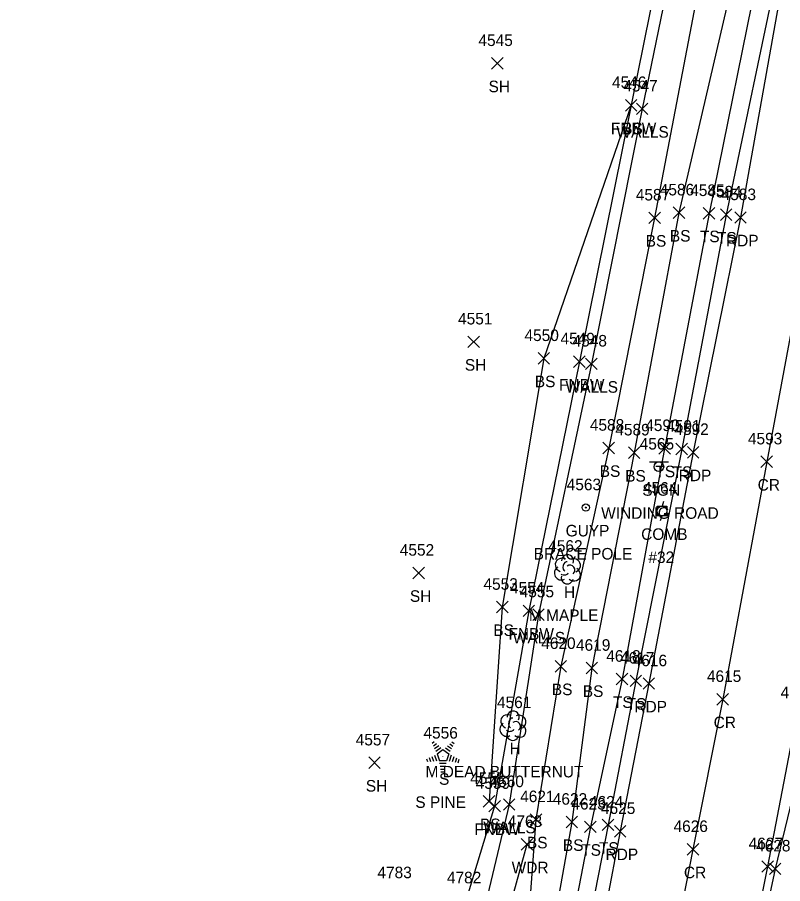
# Model space of a CAD drawing. Extents: x 1678863 to 1683592, y 407783 to 418211.
# Drawn here: x 1680118.7 to 1680251.2, y 412556.9 to 412706.9 of the extents above; entities that cross this region are included whole.
import ezdxf

# ---------------------------------------------------------------- set-up
doc = ezdxf.new("R2010")
doc.units = 0
for name, color, linetype in [('L_A', 7, 'Continuous'), ('L_C', 7, 'Continuous'), ('L_I', 7, 'Continuous'), ('L_TIC', 7, 'Continuous'), ('LAWA', 7, 'Continuous'), ('LELB', 7, 'Continuous'), ('LFNC', 7, 'Continuous'), ('LTC', 7, 'Continuous'), ('LTD', 7, 'Continuous'), ('LWS', 7, 'Continuous'), ('P_A', 7, 'Continuous'), ('P_I', 7, 'Continuous'), ('P_TIC', 7, 'Continuous'), ('PET', 7, 'Continuous'), ('PRC', 7, 'Continuous'), ('S_A', 7, 'Continuous'), ('S_C', 7, 'Continuous'), ('S_I', 7, 'Continuous'), ('SSGN', 7, 'Continuous'), ('U_A', 7, 'Continuous'), ('U_C', 7, 'Continuous'), ('U_I', 7, 'Continuous'), ('UP', 7, 'Continuous'), ('UPGW', 7, 'Continuous')]:
    doc.layers.add(name, color=color, linetype=linetype)

msp = doc.modelspace()

# ---------------------------------------------------------------- linework, layer by layer
at = {"layer": 'L_TIC'}
for points in [[(1680200.8, 412697.96), (1680202.8, 412699.96)], [(1680202.8, 412697.96), (1680200.8, 412699.96)], [(1680223.98, 412690.69), (1680225.98, 412692.69)], [(1680225.98, 412690.69), (1680223.98, 412692.69)], [(1680223.98, 412690.69), (1680225.98, 412692.69)], [(1680225.98, 412690.69), (1680223.98, 412692.69)], [(1680225.88, 412690.09), (1680227.88, 412692.09)], [(1680227.88, 412690.09), (1680225.88, 412692.09)], [(1680232.25, 412672.09), (1680234.25, 412674.09)], [(1680234.25, 412672.09), (1680232.25, 412674.09)], [(1680237.47, 412671.98), (1680239.47, 412673.98)], [(1680239.47, 412671.98), (1680237.47, 412673.98)], [(1680228.05, 412671.21), (1680230.05, 412673.21)], [(1680230.05, 412671.21), (1680228.05, 412673.21)], [(1680240.43, 412671.74), (1680242.43, 412673.74)], [(1680242.43, 412671.74), (1680240.43, 412673.74)], [(1680196.7, 412649.74), (1680198.7, 412651.74)], [(1680198.7, 412649.74), (1680196.7, 412651.74)], [(1680208.86, 412646.87), (1680210.86, 412648.87)], [(1680210.86, 412646.87), (1680208.86, 412648.87)], [(1680215.02, 412646.3), (1680217.02, 412648.3)], [(1680217.02, 412646.3), (1680215.02, 412648.3)], [(1680217.1, 412645.92), (1680219.1, 412647.92)], [(1680219.1, 412645.92), (1680217.1, 412647.92)], [(1680220.09, 412631.34), (1680222.09, 412633.34)], [(1680222.09, 412631.34), (1680220.09, 412633.34)], [(1680224.51, 412630.52), (1680226.51, 412632.52)], [(1680226.51, 412630.52), (1680224.51, 412632.52)], [(1680229.77, 412631.28), (1680231.77, 412633.28)], [(1680231.77, 412631.28), (1680229.77, 412633.28)], [(1680232.74, 412631.17), (1680234.74, 412633.17)], [(1680234.74, 412631.17), (1680232.74, 412633.17)], [(1680187.18, 412609.7), (1680189.18, 412611.7)], [(1680189.18, 412609.7), (1680187.18, 412611.7)], [(1680201.67, 412603.79), (1680203.67, 412605.79)], [(1680203.67, 412603.79), (1680201.67, 412605.79)], [(1680206.26, 412603.15), (1680208.26, 412605.15)], [(1680208.26, 412603.15), (1680206.26, 412605.15)], [(1680207.94, 412602.49), (1680209.94, 412604.49)], [(1680209.94, 412602.49), (1680207.94, 412604.49)], [(1680211.81, 412593.54), (1680213.81, 412595.54)], [(1680213.81, 412593.54), (1680211.81, 412595.54)], [(1680217.17, 412593.23), (1680219.17, 412595.23)], [(1680219.17, 412593.23), (1680217.17, 412595.23)], [(1680222.41, 412591.33), (1680224.41, 412593.33)], [(1680224.41, 412591.33), (1680222.41, 412593.33)], [(1680224.8, 412591.02), (1680226.8, 412593.02)], [(1680226.8, 412591.02), (1680224.8, 412593.02)], [(1680179.55, 412576.84), (1680181.55, 412578.84)], [(1680181.55, 412576.84), (1680179.55, 412578.84)], [(1680199.37, 412570.16), (1680201.37, 412572.16)], [(1680201.37, 412570.16), (1680199.37, 412572.16)], [(1680200.33, 412569.32), (1680202.33, 412571.32)], [(1680202.33, 412569.32), (1680200.33, 412571.32)], [(1680202.86, 412569.61), (1680204.86, 412571.61)], [(1680204.86, 412569.61), (1680202.86, 412571.61)], [(1680207.5, 412567.01), (1680209.5, 412569.01)], [(1680209.5, 412567.01), (1680207.5, 412569.01)], [(1680213.71, 412566.57), (1680215.71, 412568.57)], [(1680215.71, 412566.57), (1680213.71, 412568.57)], [(1680216.93, 412565.73), (1680218.93, 412567.73)], [(1680218.93, 412565.73), (1680216.93, 412567.73)], [(1680219.98, 412566.08), (1680221.98, 412568.08)], [(1680221.98, 412566.08), (1680219.98, 412568.08)], [(1680205.93, 412562.7), (1680207.93, 412564.7)], [(1680207.93, 412562.7), (1680205.93, 412564.7)], [(1680248.92, 412558.47), (1680250.92, 412560.47)], [(1680250.92, 412558.47), (1680248.92, 412560.47)]]:
    msp.add_lwpolyline(points, dxfattribs=at)
at = {"layer": 'LAWA'}
msp.add_lwpolyline([(1680206.93, 412563.7), (1680202.04, 412545.92), (1680195.91, 412512.78), (1680188.89, 412485.66), (1680186.26, 412471.76), (1680180.56, 412450.61), (1680168.77, 412423.38), (1680176.3, 412418.61), (1680169.98, 412398.15), (1680162.84, 412369.71), (1680155.02, 412336.92), (1680137.08, 412306.47), (1680135.2, 412293), (1680118.69, 412249.85)], dxfattribs=at)
at = {"layer": 'LELB'}
for points in [[(1680264.76, 412811.55), (1680263.36, 412796.82), (1680259.13, 412765.17), (1680254.89, 412741.7), (1680250.64, 412716.52), (1680241.43, 412672.74), (1680233.74, 412632.17), (1680225.8, 412592.02), (1680220.98, 412567.08), (1680215.74, 412540.31), (1680209.94, 412509.25), (1680204.22, 412481.07), (1680197.27, 412449.21), (1680193.18, 412427.19), (1680186.13, 412390.36), (1680174.63, 412348.27), (1680162.56, 412311.44), (1680153.21, 412285.21), (1680144.52, 412262.81), (1680134.21, 412242.14)], [(1680249.49, 412768.2), (1680249.55, 412758.24), (1680243.8, 412718.57), (1680233.25, 412673.09), (1680225.51, 412631.52), (1680218.17, 412594.23), (1680214.71, 412567.57), (1680210.01, 412541.36), (1680205.47, 412510.43), (1680201.22, 412481.17), (1680196.31, 412449.36), (1680192.42, 412427.44), (1680185.73, 412390.56), (1680174.21, 412348.31), (1680162.14, 412311.42), (1680152.66, 412285.29), (1680142.36, 412263.76), (1680132.21, 412242.7)], [(1680245.33, 412759.55), (1680238.15, 412719.92), (1680229.05, 412672.21), (1680221.09, 412632.34), (1680212.81, 412594.54), (1680208.5, 412568.01), (1680206.55, 412542.12), (1680201.64, 412511.16), (1680199.02, 412481.87), (1680194.17, 412449.89), (1680191.64, 412427.54), (1680187.79, 412410.87)], [(1680247.45, 412717.1), (1680238.47, 412672.98), (1680230.77, 412632.28), (1680223.41, 412592.33), (1680217.93, 412566.73), (1680212.88, 412540.48)], [(1680224.98, 412691.69), (1680209.86, 412647.87), (1680202.67, 412604.79), (1680200.37, 412571.16)], [(1680298.44, 412568.57), (1680284.88, 412583.01), (1680266.88, 412595.61), (1680260.41, 412601.01), (1680256.27, 412585.74), (1680249.92, 412559.47), (1680243.91, 412531.33), (1680236.6, 412492.51), (1680228.82, 412454.39), (1680218.5, 412406.89), (1680208.69, 412367.35), (1680198.1, 412331.27), (1680190.23, 412308.46), (1680180.36, 412277.86), (1680168.7, 412243.07)]]:
    msp.add_lwpolyline(points, dxfattribs=at)
at = {"layer": 'LFNC'}
msp.add_lwpolyline([(1680218.33, 412787.64), (1680231.24, 412777.54), (1680236.8, 412767.88), (1680237.55, 412751.41), (1680232.55, 412729.19), (1680224.98, 412691.69), (1680216.02, 412647.3), (1680207.26, 412604.15), (1680201.33, 412570.32), (1680196.34, 412553.95), (1680191.84, 412524.59), (1680188.15, 412511.78), (1680185.17, 412500.91), (1680174.35, 412504.66)], dxfattribs=at)
at = {"layer": 'LTC'}
for p, q in [((1680190.53, 412581.23), (1680190.89, 412581.49)), ((1680190.74, 412580.77), (1680191.27, 412581.15)), ((1680193.56, 412581.12), (1680194.11, 412580.72)), ((1680193.93, 412581.47), (1680194.35, 412581.17)), ((1680190.95, 412580.3), (1680191.66, 412580.81)), ((1680191.16, 412579.83), (1680192.04, 412580.47)), ((1680191.39, 412579.38), (1680192.4, 412580.11)), ((1680191.39, 412579.38), (1680191.77, 412578.19)), ((1680192.4, 412580.11), (1680193.39, 412579.39)), ((1680192.82, 412580.43), (1680193.63, 412579.84)), ((1680193.39, 412579.39), (1680193, 412578.19)), ((1680193.19, 412580.77), (1680193.87, 412580.28)), ((1680189.56, 412578.51), (1680189.72, 412578.04)), ((1680190.02, 412578.73), (1680190.23, 412578.07)), ((1680190.48, 412578.94), (1680190.75, 412578.11)), ((1680190.93, 412579.16), (1680191.26, 412578.14)), ((1680193, 412578.19), (1680191.77, 412578.19)), ((1680193.83, 412579.12), (1680193.49, 412578.08)), ((1680194.28, 412578.87), (1680193.99, 412577.98)), ((1680194.72, 412578.62), (1680194.48, 412577.89)), ((1680195.17, 412578.37), (1680194.98, 412577.79)), ((1680192.96, 412577.69), (1680191.82, 412577.69)), ((1680192.88, 412577.19), (1680191.89, 412577.19)), ((1680192.8, 412576.69), (1680191.97, 412576.69)), ((1680192.71, 412576.19), (1680192.04, 412576.19))]:
    msp.add_line(p, q, dxfattribs=at)
at = {"layer": 'LTD'}
for p, q in [((1680213.92, 412611.38), (1680213.92, 412611.38)), ((1680213.92, 412611.38), (1680213.92, 412611.38)), ((1680204.49, 412584.3), (1680204.49, 412584.3)), ((1680204.49, 412584.3), (1680204.49, 412584.3))]:
    msp.add_line(p, q, dxfattribs=at)
for centre in [(1680213.97, 412612.82), (1680204.54, 412585.73)]:
    msp.add_arc(centre, 1.05, 335.5272, 180.9563, dxfattribs=at)
for centre, major_axis, ratio, start_param, end_param in [((1680213.13, 412612.05), (1.21, -0.51), 0.895232, 1.570796, 4.712389), ((1680213.72, 412611.84), (-0.208, -0.792), 0.645439, 3.141593, 6.283185), ((1680214.97, 412611.97), (-1.14, -0.48), 0.949671, 1.570796, 4.712389), ((1680212.84, 412610.67), (0.58, -1.04), 0.959034, 3.141593, 6.283185), ((1680214.42, 412611.22), (-0.5, 0.667), 0.989748, 3.141593, 6.283185), ((1680214.92, 412610.55), (-1.09, 0.79), 0.841452, 1.570796, 4.712389), ((1680213.92, 412609.88), (0.26, 1.06), 0.942809, 1.570796, 4.712389), ((1680213.47, 412610.63), (-0.625, -0.083), 0.423636, 0, 3.141593), ((1680203.7, 412584.96), (1.21, -0.51), 0.895232, 1.570796, 4.712389), ((1680204.29, 412584.76), (-0.208, -0.792), 0.645439, 3.141593, 6.283185), ((1680205.54, 412584.88), (-1.14, -0.48), 0.949671, 1.570796, 4.712389), ((1680203.41, 412583.59), (0.58, -1.04), 0.959034, 3.141593, 6.283185), ((1680204.99, 412584.13), (-0.5, 0.667), 0.989748, 3.141593, 6.283185), ((1680205.49, 412583.46), (-1.09, 0.79), 0.841452, 1.570796, 4.712389), ((1680204.49, 412582.8), (0.26, 1.06), 0.942809, 1.570796, 4.712389), ((1680204.04, 412583.55), (-0.625, -0.083), 0.423636, 0, 3.141593)]:
    msp.add_ellipse(centre, major_axis=major_axis, ratio=ratio, start_param=start_param, end_param=end_param, dxfattribs=at)
at = {"layer": 'LWS'}
msp.add_lwpolyline([(1680245.37, 412777.27), (1680244.27, 412770.72), (1680239.06, 412752.16), (1680234.49, 412728.17), (1680226.88, 412691.09), (1680218.1, 412646.92), (1680208.94, 412603.49), (1680203.86, 412570.61), (1680197.52, 412543.94), (1680191.67, 412514.8), (1680187.87, 412497.52)], dxfattribs=at)
at = {"layer": 'P_TIC'}
for points in [[(1680242.91, 412671.27), (1680244.91, 412673.27)], [(1680244.91, 412671.27), (1680242.91, 412673.27)], [(1680234.73, 412630.6), (1680236.73, 412632.6)], [(1680236.73, 412630.6), (1680234.73, 412632.6)], [(1680247.46, 412628.97), (1680249.46, 412630.97)], [(1680249.46, 412628.97), (1680247.46, 412630.97)], [(1680227.05, 412590.55), (1680229.05, 412592.55)], [(1680229.05, 412590.55), (1680227.05, 412592.55)], [(1680239.84, 412587.83), (1680241.84, 412589.83)], [(1680241.84, 412587.83), (1680239.84, 412589.83)], [(1680222.07, 412564.97), (1680224.07, 412566.97)], [(1680224.07, 412564.97), (1680222.07, 412566.97)], [(1680234.69, 412561.84), (1680236.69, 412563.84)], [(1680236.69, 412561.84), (1680234.69, 412563.84)], [(1680247.62, 412558.86), (1680249.62, 412560.86)], [(1680249.62, 412558.86), (1680247.62, 412560.86)]]:
    msp.add_lwpolyline(points, dxfattribs=at)
at = {"layer": 'PET'}
for points in [[(1680296.3, 412834.01), (1680292.92, 412809.88), (1680289.09, 412781.37), (1680282.07, 412737.34), (1680277.46, 412709.86), (1680269.38, 412667.98), (1680262.24, 412629.4), (1680258.01, 412607.41), (1680253.6, 412586.01), (1680248.62, 412559.86), (1680242.91, 412531.6), (1680235.26, 412492.91), (1680227.56, 412454.34), (1680216.99, 412407.09), (1680207.45, 412367.83), (1680196.86, 412331.66), (1680189.42, 412308.79), (1680178.4, 412278.7), (1680165.09, 412243.62)], [(1680269.63, 412829.2), (1680265.04, 412796.13), (1680259.96, 412765.02), (1680256.28, 412741.52), (1680251.79, 412716.36), (1680243.91, 412672.27), (1680235.73, 412631.6), (1680228.05, 412591.55), (1680223.07, 412565.97), (1680218.11, 412539.91), (1680211.61, 412508.58), (1680205.85, 412480.93), (1680199.66, 412448.83), (1680195.01, 412427.07), (1680186.54, 412390.39), (1680175.26, 412348.31), (1680163.41, 412311.1), (1680153.81, 412285.2), (1680145.32, 412262.57), (1680136.24, 412241.39)]]:
    msp.add_lwpolyline(points, dxfattribs=at)
at = {"layer": 'PRC'}
msp.add_lwpolyline([(1680281.38, 412827.12), (1680276.54, 412794.32), (1680271.51, 412761.65), (1680263.6, 412713.37), (1680255.9, 412669.93), (1680248.46, 412629.97), (1680240.84, 412588.83), (1680235.69, 412562.84), (1680230.13, 412534.53), (1680222.13, 412495.39), (1680214.42, 412458.66), (1680203.73, 412409.82), (1680194.11, 412372.14), (1680183.59, 412335.84), (1680176.01, 412313.28), (1680165.53, 412283.79), (1680155.94, 412258.65)], dxfattribs=at)
at = {"layer": 'SSGN'}
for p, q in [((1680228.14, 412629.93), (1680231.47, 412629.93)), ((1680229.78, 412629.1), (1680229.78, 412629.1))]:
    msp.add_line(p, q, dxfattribs=at)
msp.add_circle((1680229.78, 412629.1), 0.833, dxfattribs=at)
at = {"layer": 'UP'}
for p, q in [((1680230.58, 412623.1), (1680230.33, 412622.27)), ((1680229.5, 412620.6), (1680229.5, 412622.27)), ((1680229.5, 412622.27), (1680231.16, 412622.27)), ((1680230.33, 412621.43), (1680230.33, 412621.43)), ((1680231.16, 412622.27), (1680231.16, 412620.6)), ((1680231.16, 412620.6), (1680229.5, 412620.6)), ((1680230.08, 412619.77), (1680230.33, 412620.6))]:
    msp.add_line(p, q, dxfattribs=at)
msp.add_circle((1680230.33, 412621.43), 0.833, dxfattribs=at)
at = {"layer": 'UPGW'}
for radius in [0.625, 0.0833]:
    msp.add_circle((1680217.13, 412622.03), radius, dxfattribs=at)

# ---------------------------------------------------------------- texts
at = {"layer": 'L_A'}
for s, p in [('SH', (1680200.29, 412693.96)), ('FNBW', (1680221.46, 412686.69)), ('WALLS', (1680222.43, 412686.09)), ('BS', (1680223.42, 412686.69)), ('BS', (1680231.69, 412668.09)), ('TS', (1680236.88, 412667.98)), ('TS', (1680239.84, 412667.74)), ('BS', (1680227.5, 412667.21)), ('SH', (1680196.19, 412645.74)), ('BS', (1680208.3, 412642.87)), ('FNBW', (1680212.49, 412642.3)), ('WALLS', (1680213.64, 412641.92)), ('BS', (1680219.54, 412627.34)), ('TS', (1680229.18, 412627.28)), ('TS', (1680232.15, 412627.17)), ('BS', (1680223.95, 412626.52)), ('H', (1680213.36, 412606.38)), ('SH', (1680186.67, 412605.7)), ('BS', (1680201.12, 412599.79)), ('FNBW', (1680203.74, 412599.15)), ('WALLS', (1680204.49, 412598.49)), ('BS', (1680211.25, 412589.54)), ('BS', (1680216.61, 412589.23)), ('TS', (1680221.82, 412587.33)), ('TS', (1680224.21, 412587.02)), ('H', (1680203.93, 412579.3)), ('SH', (1680179.04, 412572.84)), ('S', (1680191.72, 412574.02)), ('BS', (1680198.82, 412566.16)), ('WALLS', (1680199.4, 412565.61)), ('FNBW', (1680197.81, 412565.32)), ('BS', (1680206.94, 412563.01)), ('BS', (1680213.16, 412562.57)), ('TS', (1680216.34, 412561.73)), ('TS', (1680219.39, 412562.08)), ('WDR', (1680204.29, 412558.7))]:
    msp.add_text(s, height=2, dxfattribs=at).set_placement(p)
at = {"layer": 'L_C'}
for s, p in [('M MAPLE', (1680207.28, 412602.38)), ('M DEAD BUTTERNUT', (1680189.38, 412575.3)), ('S PINE', (1680187.61, 412570.02))]:
    msp.add_text(s, height=2, dxfattribs=at).set_placement(p)
at = {"layer": 'L_I'}
for s, p in [('4545', (1680198.54, 412701.96)), ('4546', (1680221.67, 412694.69)), ('4546', (1680221.67, 412694.69)), ('4547', (1680223.62, 412694.09)), ('4587', (1680225.79, 412675.21)), ('4586', (1680229.94, 412676.09)), ('4585', (1680235.21, 412675.98)), ('4584', (1680238.17, 412675.74)), ('4551', (1680195.01, 412653.74)), ('4550', (1680206.51, 412650.87)), ('4549', (1680212.75, 412650.3)), ('4548', (1680214.84, 412649.92)), ('4588', (1680217.83, 412635.34)), ('4589', (1680222.24, 412634.52)), ('4590', (1680227.42, 412635.28)), ('4591', (1680231.05, 412635.17)), ('4552', (1680184.92, 412613.7)), ('4562', (1680210.62, 412614.38)), ('4553', (1680199.41, 412607.79)), ('4554', (1680204, 412607.15)), ('4555', (1680205.68, 412606.49)), ('4620', (1680209.41, 412597.54)), ('4619', (1680215.43, 412597.23)), ('4618', (1680220.67, 412595.33)), ('4617', (1680223.06, 412595.02)), ('4561', (1680201.75, 412587.3)), ('4556', (1680189.02, 412582.02)), ('4557', (1680177.29, 412580.84)), ('4558', (1680197.11, 412574.16)), ('4559', (1680198.07, 412573.32)), ('4560', (1680200.46, 412573.61)), ('4621', (1680205.76, 412571.01)), ('4622', (1680211.41, 412570.57)), ('4624', (1680217.68, 412570.08)), ('4623', (1680214.63, 412569.73)), ('4763', (1680203.62, 412566.7)), ('4628', (1680246.62, 412562.47)), ('4783', (1680181.05, 412557.84)), ('4782', (1680193.08, 412556.95)), ('4782', (1680193.08, 412556.95))]:
    msp.add_text(s, height=2, dxfattribs=at).set_placement(p)
at = {"layer": 'LTC'}
msp.add_text('.', height=1.04, rotation=270, dxfattribs=at).set_placement((1680192.28, 412579.13))
at = {"layer": 'P_A'}
for s, p in [('RDP', (1680241.4, 412667.27)), ('RDP', (1680233.22, 412626.6)), ('CR', (1680246.89, 412624.97)), ('RDP', (1680225.54, 412586.55)), ('CR', (1680239.27, 412583.83)), ('RDP', (1680220.55, 412560.97)), ('CR', (1680234.12, 412557.84))]:
    msp.add_text(s, height=2, dxfattribs=at).set_placement(p)
at = {"layer": 'P_I'}
for s, p in [('4583', (1680240.65, 412675.27)), ('4592', (1680232.47, 412634.6)), ('4593', (1680245.2, 412632.97)), ('4616', (1680225.25, 412594.55)), ('4615', (1680238.1, 412591.83)), ('4614', (1680250.86, 412589.01)), ('4625', (1680219.76, 412568.97)), ('4626', (1680232.32, 412565.84)), ('4627', (1680245.32, 412562.86))]:
    msp.add_text(s, height=2, dxfattribs=at).set_placement(p)
at = {"layer": 'S_A'}
msp.add_text('SIGN', height=2, dxfattribs=at).set_placement((1680226.92, 412624.08))
at = {"layer": 'S_C'}
msp.add_text('WINDING ROAD', height=2, dxfattribs=at).set_placement((1680219.79, 412620.08))
at = {"layer": 'S_I'}
msp.add_text('4565', height=2, dxfattribs=at).set_placement((1680226.46, 412632.08))
at = {"layer": 'U_A'}
for s, p in [('GUYP', (1680213.64, 412617.03)), ('COMB', (1680226.72, 412616.43))]:
    msp.add_text(s, height=2, dxfattribs=at).set_placement(p)
at = {"layer": 'U_C'}
for s, p in [('BRACE POLE', (1680208.09, 412613.03)), ('#32', (1680227.97, 412612.43))]:
    msp.add_text(s, height=2, dxfattribs=at).set_placement(p)
at = {"layer": 'U_I'}
for s, p in [('4563', (1680213.82, 412625.03)), ('4564', (1680227.02, 412624.43))]:
    msp.add_text(s, height=2, dxfattribs=at).set_placement(p)

doc.saveas('drawing.dxf')
